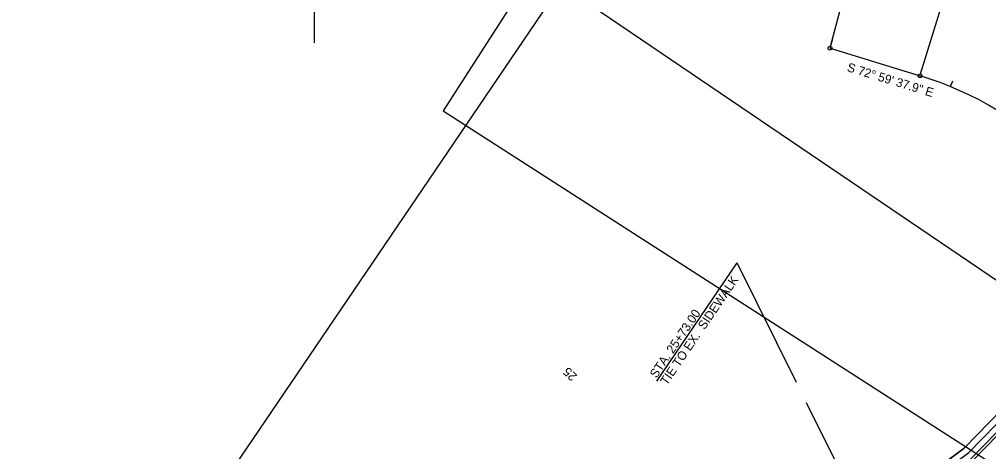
# Model space of a CAD drawing. Extents: x 1974386 to 1979988, y 776712 to 784860.
# Drawn here: x 1975893 to 1976659, y 779824 to 780166 of the extents above; entities that cross this region are included whole.
import ezdxf

# ---------------------------------------------------------------- set-up
doc = ezdxf.new("R2010")
doc.units = 0
for name, color, linetype in [('Old_Level_1', 7, 'Continuous'), ('Prop Conc 2ft 6in Curb and Gutter', 7, 'Continuous'), ('Prop Conc 4in Sidewalk', 7, 'Continuous'), ('Prop DSN Text', 7, 'Continuous'), ('Prop EOT', 7, 'Continuous'), ('Prop Horizontal Alignment', 7, 'Continuous'), ('Prop Horizontal Alignment Direction Label', 7, 'Continuous'), ('Prop Horizontal Alignment Station Label', 7, 'Continuous'), ('Prop Horizontal Alignment Tick Label', 7, 'Continuous'), ('Prop Horizontal Alignment Tick Large', 7, 'Continuous'), ('Prop Horizontal Alignment Tick Small', 7, 'Continuous'), ('Sheet Layout Plan Border', 7, 'Continuous')]:
    doc.layers.add(name, color=color, linetype=linetype)

msp = doc.modelspace()

# ---------------------------------------------------------------- linework, layer by layer
at = {"layer": 'Old_Level_1'}
msp.add_line((1976126.13, 780147.76), (1976126, 780214.82), dxfattribs=at)
at = {"layer": 'Prop Conc 2ft 6in Curb and Gutter'}
msp.add_line((1976546.47, 779717.4), (1976765.69, 779942.36), dxfattribs=at)
at = {"layer": 'Prop Conc 4in Sidewalk'}
for points in [[(1976559.67, 779760.84), (1976643.63, 779823.56), (1976762.46, 779945.49)], [(1976559.67, 779760.84), (1976643.63, 779823.56), (1976762.46, 779945.49)], [(1976569.28, 779774.25), (1976640.03, 779827.02), (1976758.88, 779948.99)], [(1976758.88, 779948.98), (1976640.03, 779827.02), (1976569.28, 779774.25)]]:
    msp.add_lwpolyline(points, dxfattribs=at)
at = {"layer": 'Prop DSN Text'}
for p, q in [((1976396.94, 779880.11), (1976460.34, 779973.55)), ((1976507.34, 779879.03), (1976460.34, 779973.55)), ((1976539.33, 779814.7), (1976515.35, 779862.91))]:
    msp.add_line(p, q, dxfattribs=at)
at = {"layer": 'Prop EOT'}
msp.add_line((1976550.82, 779719), (1976767.11, 779940.96), dxfattribs=at)
at = {"layer": 'Prop Horizontal Alignment'}
msp.add_line((1976533.81, 780143.46), (1976605.04, 780121.67), dxfattribs=at)
msp.add_line((1976533.81, 780143.46), (1976605.04, 780121.67), dxfattribs=at)
msp.add_arc((1976525.24, 779860.76), 272.84, 44.7243, 72.99385, dxfattribs=at)
msp.add_arc((1976525.24, 779860.76), 272.84, 44.7243, 72.99385, dxfattribs=at)
at = {"layer": 'Prop Horizontal Alignment Station Label'}
for p, q in [((1976534.24, 780144.89), (1976579.75, 780318.58)), ((1976605.48, 780123.1), (1976643.44, 780247.22))]:
    msp.add_line(p, q, dxfattribs=at)
for centre in [(1976533.81, 780143.46), (1976605.04, 780121.67)]:
    msp.add_circle(centre, 1.5, dxfattribs=at)
at = {"layer": 'Prop Horizontal Alignment Tick Large'}
msp.add_line((1976533.81, 780143.46), (1976536.15, 780151.11), dxfattribs=at)
at = {"layer": 'Prop Horizontal Alignment Tick Small'}
msp.add_line((1976629.05, 780113.08), (1976630.95, 780117.71), dxfattribs=at)
at = {"layer": 'Sheet Layout Plan Border'}
for points in [[(1977111.11, 779526.05), (1977868.38, 780703.57), (1976985.24, 781271.52), (1976227.97, 780094)], [(1976403.86, 778445.65), (1977189.89, 779604.17), (1976321, 780193.69), (1975534.97, 779035.17)]]:
    msp.add_lwpolyline(points, close=True, dxfattribs=at)

# ---------------------------------------------------------------- texts
at = {"layer": 'Prop DSN Text'}
for s, p in [('TIE TO EX.  SIDEWALK', (1976404.81, 779876.31)), ('STA. 25+73.00', (1976396.54, 779881.92))]:
    msp.add_text(s, height=7, rotation=55.84408, dxfattribs=at).set_placement(p)
at = {"layer": 'Prop Horizontal Alignment Direction Label'}
msp.add_text('S 72%%d 59\' 37.9" E', height=7, rotation=342.99385, dxfattribs=at).set_placement((1976546.77, 780125.43))
at = {"layer": 'Prop Horizontal Alignment Tick Label'}
msp.add_text('25', height=7, rotation=136.68234, dxfattribs=at).set_placement((1976334.32, 779884.5))

doc.saveas('drawing.dxf')
